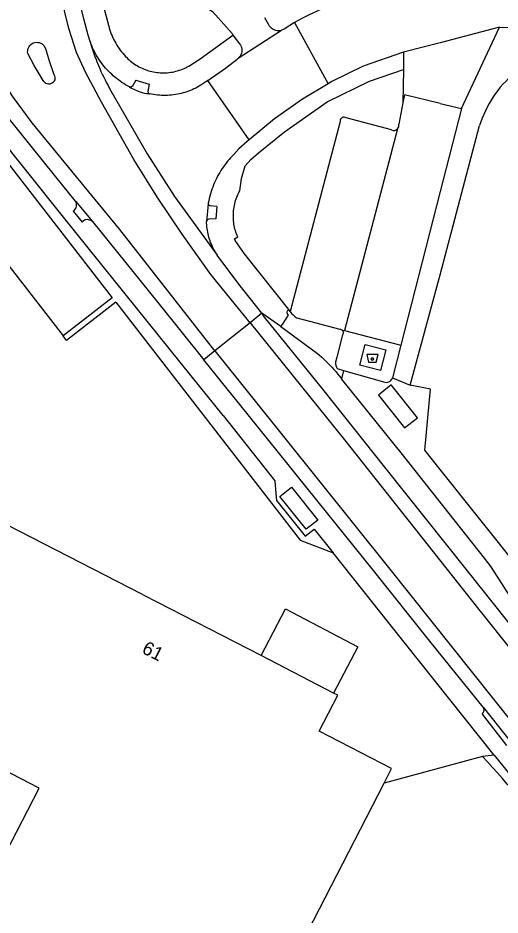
# Model space of a CAD drawing. Extents: x 194485 to 197793, y 468269 to 470822.
# Drawn here: x 194962.7 to 195005.3, y 470132.4 to 470211.6 of the extents above; entities that cross this region are included whole.
import ezdxf

# ---------------------------------------------------------------- set-up
doc = ezdxf.new("R2010")
doc.units = 0
for name, color, linetype in [('BGT grensvlak gebouwinstallatie plus 1', 7, 'Continuous'), ('BGT grensvlak onbegroeid terreindeel', 7, 'Continuous'), ('BGT grensvlak onbegroeid terreindeel LR', 7, 'Continuous'), ('BGT grensvlak pand op maaiveld', 7, 'Continuous'), ('BGT grensvlak wegdeel', 7, 'Continuous'), ('BGT puntobject bak afval apart plaats', 7, 'Continuous'), ('BGT tekst huisnummerreeks', 7, 'Continuous')]:
    doc.layers.add(name, color=color, linetype=linetype)

msp = doc.modelspace()

# ---------------------------------------------------------------- linework, layer by layer
at = {"layer": 'BGT grensvlak gebouwinstallatie plus 1'}
for p, q in [((194984.175, 470155.285), (194986.344, 470159.424)), ((194986.344, 470159.424), (194992.732, 470156.076)), ((194992.732, 470156.076), (194990.587, 470151.983))]:
    msp.add_line(p, q, dxfattribs=at)
for points in [[(194994.538, 470178.29), (194996.858, 470175.385), (194997.985, 470176.286), (194995.666, 470179.191), (194994.538, 470178.29)], [(194985.85, 470169.344), (194986.858, 470170.149), (194989.182, 470167.258), (194988.159, 470166.44), (194985.85, 470169.344)]]:
    msp.add_lwpolyline(points, dxfattribs=at)
at = {"layer": 'BGT grensvlak onbegroeid terreindeel'}
for points in [[(194971.351, 470186.487), (194967.003, 470183.119), (194966.696, 470183.514)], [(194971.351, 470186.487), (194987.623, 470165.482), (194990.541, 470164.356)], [(195004.761, 470146.507), (195003.725, 470146.37), (195003.718, 470146.368)]]:
    msp.add_lwpolyline(points, dxfattribs=at)
msp.add_arc((194976.202, 470119.132), 38.716, 13.77884, 44.70719, dxfattribs=at)
at = {"layer": 'BGT grensvlak onbegroeid terreindeel LR'}
msp.add_line((195003.718, 470146.368), (194995.051, 470144.028), dxfattribs=at)
at = {"layer": 'BGT grensvlak pand op maaiveld'}
msp.add_line((194990.587, 470151.983), (194984.175, 470155.285), dxfattribs=at)
for points in [[(194984.175, 470155.285), (194973.844, 470160.603), (194973.658, 470160.702), (194961.785, 470166.804), (194959.691, 470162.731), (194956.928, 470164.203), (194958.605, 470167.467), (194954.189, 470169.736)], [(194995.051, 470144.028), (194995.708, 470145.307), (194989.3, 470148.605), (194990.947, 470151.798), (194990.587, 470151.983)], [(194944.699, 470140.345), (194959.065, 470132.901), (194964.571, 470143.582), (194950.178, 470151.016), (194944.699, 470140.345)], [(194970.192, 470100.423), (194979.609, 470118.778), (194982.244, 470117.429), (194984.803, 470122.431), (194984.134, 470122.797), (194995.051, 470144.028)]]:
    msp.add_lwpolyline(points, dxfattribs=at)
at = {"layer": 'BGT grensvlak wegdeel'}
for p, q in [((194987.126, 470211.192), (194990.111, 470205.784)), ((194982.161, 470208.034), (194985.981, 470210.514)), ((195005.244, 470210.774), (195000, 470209.408)), ((195001.881, 470203.594), (195005.244, 470210.774)), ((195005.244, 470210.774), (195056.446, 470209.741)), ((195000, 470209.408), (194996.768, 470208.565)), ((194996.768, 470208.565), (194996.745, 470207.046)), ((194993.74, 470206.017), (194996.745, 470207.046)), ((194996.745, 470207.046), (194996.699, 470204.089)), ((194973.112, 470206.102), (194974.3, 470205.73)), ((194983.125, 470200.83), (194979.465, 470206.079)), ((194990.014, 470204.184), (194993.74, 470206.017)), ((194986.237, 470201.529), (194990.014, 470204.184)), ((194996.699, 470204.089), (194996.336, 470202.199)), ((195000, 470204.044), (195001.881, 470203.594)), ((195001.881, 470203.594), (195000, 470196.271)), ((194991.165, 470202.457), (194986.761, 470185.667)), ((194995.707, 470201.717), (194991.695, 470202.757)), ((194983.943, 470199.684), (194986.237, 470201.529)), ((194996.228, 470201.787), (194991.559, 470183.987)), ((194982.785, 470198.545), (194983.286, 470199.084)), ((194983.286, 470199.084), (194983.943, 470199.684)), ((194982.454, 470197.422), (194982.785, 470198.545)), ((194982.293, 470196.324), (194982.454, 470197.422)), ((194982.035, 470195.763), (194982.092, 470195.907)), ((194982.092, 470195.907), (194982.155, 470196.048)), ((194982.155, 470196.048), (194982.222, 470196.187)), ((194982.222, 470196.187), (194982.293, 470196.324)), ((195000, 470196.271), (194996.517, 470182.713)), ((194957.508, 470195.375), (194966.696, 470183.514)), ((194967.781, 470195.428), (194969.297, 470193.605)), ((194979.504, 470195.14), (194979.363, 470193.63)), ((194981.793, 470194.87), (194981.821, 470195.022)), ((194981.821, 470195.022), (194981.853, 470195.173)), ((194981.853, 470195.173), (194981.891, 470195.323)), ((194981.891, 470195.323), (194981.934, 470195.471)), ((194981.934, 470195.471), (194981.982, 470195.618)), ((194981.982, 470195.618), (194982.035, 470195.763)), ((194967.577, 470194.521), (194968.391, 470193.572)), ((194980.266, 470194.93), (194980.19, 470193.859)), ((194981.73, 470194.121), (194981.732, 470194.269)), ((194981.732, 470194.269), (194981.74, 470194.417)), ((194981.74, 470194.417), (194981.752, 470194.564)), ((194981.752, 470194.564), (194981.77, 470194.717)), ((194981.77, 470194.717), (194981.793, 470194.87)), ((194981.731, 470193.974), (194981.73, 470194.121)), ((194981.738, 470193.826), (194981.731, 470193.974)), ((194981.749, 470193.678), (194981.738, 470193.826)), ((194981.765, 470193.532), (194981.749, 470193.678)), ((194981.786, 470193.385), (194981.765, 470193.532)), ((194981.811, 470193.24), (194981.786, 470193.385)), ((194981.841, 470193.095), (194981.811, 470193.24)), ((194981.876, 470192.951), (194981.841, 470193.095)), ((194981.915, 470192.809), (194981.876, 470192.951)), ((194981.959, 470192.667), (194981.915, 470192.809)), ((194982.007, 470192.528), (194981.959, 470192.667)), ((194981.84, 470192.094), (194982.116, 470192.253)), ((194981.899, 470191.955), (194981.84, 470192.094)), ((194982.728, 470190.752), (194981.899, 470191.955)), ((194982.059, 470192.389), (194982.007, 470192.528)), ((194982.116, 470192.253), (194982.059, 470192.389)), ((194986.617, 470185.848), (194982.728, 470190.752)), ((194984.254, 470185.52), (194983.21, 470184.681)), ((194985.936, 470184.339), (194984.254, 470185.52)), ((194986.493, 470185.603), (194986.525, 470185.735)), ((194986.521, 470185.47), (194986.493, 470185.603)), ((194986.525, 470185.735), (194986.617, 470185.848)), ((194986.761, 470185.667), (194986.617, 470185.848)), ((194986.061, 470184.53), (194986.602, 470185.361)), ((194986.602, 470185.361), (194986.521, 470185.47)), ((194983.21, 470184.681), (194980.103, 470182.186)), ((194985.936, 470184.339), (194986.061, 470184.53)), ((194991.294, 470184.055), (194991.559, 470183.987)), ((194991.559, 470183.987), (194996.517, 470182.713)), ((194996.517, 470182.713), (194995.774, 470179.82)), ((194980.103, 470182.186), (194979.129, 470181.403)), ((194990.902, 470180.628), (194991.457, 470180.468)), ((194991.457, 470180.468), (194991.292, 470179.717)), ((194991.457, 470180.468), (194995.104, 470179.419)), ((194995.774, 470179.82), (194997.335, 470179.171)), ((195010.791, 470158.173), (195000, 470171.718)), ((195003.779, 470150.737), (195006.502, 470147.326)), ((195003.699, 470150.132), (195005.859, 470147.365)), ((195004.761, 470146.507), (195007.698, 470142.82))]:
    msp.add_line(p, q, dxfattribs=at)
for points in [[(194980.103, 470182.186), (194971.719, 470192.904), (194967.463, 470198.054), (194963.962, 470202.328), (194962.223, 470204.689), (194960.673, 470207.087), (194959.498, 470209.448), (194958.738, 470211.291), (194958.082, 470213.399), (194957.69, 470215.496), (194957.31, 470218.318), (194957.202, 470221.395), (194957.651, 470224.332), (194958.365, 470227.074), (194959.402, 470229.838), (194960.334, 470232.349), (194964.43, 470242.629), (194967.101, 470249.367), (194974.852, 470268.643)], [(194983.21, 470184.681), (194979.75, 470188.94), (194977.217, 470192.511), (194975.04, 470195.736), (194972.944, 470199.1), (194970.095, 470204.15), (194968.668, 470206.799), (194967.896, 470208.55), (194967.217, 470210.646), (194966.468, 470213.687), (194965.715, 470217.72), (194965.45, 470220.278), (194965.278, 470222.892), (194965.128, 470225.715), (194965.411, 470230.35), (194965.826, 470233.379), (194966.54, 470236.535), (194966.966, 470238.321), (194967.841, 470241.201)], [(194969.745, 470214.63), (194970.372, 470214.671), (194970.532, 470214.657), (194973.192, 470214.524), (194975.982, 470214.15), (194977.779, 470213.574), (194979.905, 470212.147), (194981.631, 470210.207), (194981.681, 470210.081), (194981.691, 470210.068)], [(194969.745, 470214.63), (194970.827, 470210.504), (194970.888, 470210.334), (194970.953, 470210.166), (194971.023, 470209.999), (194971.098, 470209.835), (194971.177, 470209.673), (194971.261, 470209.513), (194971.35, 470209.355), (194971.442, 470209.2), (194971.539, 470209.048), (194971.64, 470208.898), (194971.746, 470208.752), (194971.855, 470208.608), (194971.969, 470208.467), (194972.086, 470208.33), (194972.207, 470208.196), (194972.312, 470208.087), (194972.42, 470207.982), (194972.532, 470207.88), (194972.647, 470207.782), (194972.765, 470207.688), (194972.886, 470207.598), (194973.01, 470207.512), (194973.137, 470207.43), (194973.267, 470207.352), (194973.399, 470207.279), (194973.533, 470207.21), (194973.67, 470207.146), (194973.809, 470207.086), (194973.949, 470207.031), (194974.092, 470206.98), (194974.236, 470206.935), (194974.381, 470206.894), (194974.528, 470206.858), (194974.676, 470206.826), (194974.824, 470206.8), (194974.974, 470206.779), (194975.127, 470206.762), (194975.28, 470206.751), (194975.433, 470206.745), (194975.587, 470206.744), (194975.74, 470206.748), (194975.893, 470206.757), (194976.046, 470206.772), (194976.198, 470206.792), (194976.35, 470206.816), (194976.5, 470206.846), (194976.65, 470206.881), (194976.798, 470206.921), (194976.945, 470206.966), (194977.09, 470207.016), (194977.233, 470207.071), (194977.375, 470207.13), (194977.514, 470207.195), (194977.651, 470207.263), (194977.786, 470207.337), (194978.803, 470207.977), (194981.691, 470210.068)], [(194969.08, 470209.51), (194969.016, 470209.695), (194968.958, 470209.882), (194968.905, 470210.07), (194968.526, 470211.519), (194968.065, 470213.446), (194968.035, 470213.568)], [(194984.471, 470211.62), (194984.845, 470211.003), (194984.907, 470210.9), (194984.98, 470210.806), (194985.065, 470210.722), (194985.159, 470210.648), (194985.261, 470210.586), (194985.371, 470210.538), (194985.485, 470210.503), (194985.609, 470210.482), (194985.734, 470210.476), (194985.859, 470210.487), (194985.981, 470210.514)], [(194987.126, 470211.192), (194986.211, 470210.613), (194986.099, 470210.556), (194985.981, 470210.514)], [(194981.691, 470210.068), (194982.286, 470209.297), (194982.357, 470209.195), (194982.414, 470209.084), (194982.455, 470208.967), (194982.479, 470208.845), (194982.487, 470208.721), (194982.477, 470208.597), (194982.448, 470208.468), (194982.401, 470208.345), (194982.337, 470208.23), (194982.256, 470208.125), (194982.161, 470208.034)], [(194963.584, 470208.442), (194963.567, 470208.569), (194963.57, 470208.697), (194963.593, 470208.823), (194963.635, 470208.944), (194963.695, 470209.057), (194963.772, 470209.159), (194963.863, 470209.249), (194963.968, 470209.323), (194964.082, 470209.38), (194964.207, 470209.42), (194964.338, 470209.439), (194964.469, 470209.437), (194964.599, 470209.415), (194964.723, 470209.372), (194964.839, 470209.311), (194964.944, 470209.231), (194965.035, 470209.136), (194965.16, 470208.805), (194965.453, 470207.9), (194965.893, 470206.6), (194965.948, 470206.493), (194965.978, 470206.376), (194965.982, 470206.255), (194965.96, 470206.137), (194965.912, 470206.026), (194965.842, 470205.928), (194965.751, 470205.848), (194965.646, 470205.789), (194965.529, 470205.754), (194965.407, 470205.747), (194965.286, 470205.766), (194965.173, 470205.811), (194965.072, 470205.88), (194964.989, 470205.97), (194964.928, 470206.076), (194964.152, 470207.396), (194963.584, 470208.442)], [(194972.551, 470205.51), (194972.382, 470205.602), (194972.216, 470205.697), (194972.053, 470205.798), (194971.892, 470205.902), (194971.733, 470206.011), (194971.578, 470206.124), (194971.426, 470206.241), (194971.277, 470206.362), (194971.131, 470206.487), (194970.989, 470206.615), (194970.85, 470206.748), (194970.714, 470206.884), (194970.582, 470207.023), (194970.454, 470207.166), (194970.33, 470207.312), (194970.207, 470207.464), (194970.089, 470207.62), (194969.974, 470207.778), (194969.864, 470207.94), (194969.759, 470208.104), (194969.658, 470208.272), (194969.561, 470208.442), (194969.469, 470208.614), (194969.381, 470208.789), (194969.299, 470208.966), (194969.221, 470209.146), (194969.148, 470209.327), (194969.08, 470209.51)], [(194996.768, 470208.565), (194993.191, 470207.34), (194990.435, 470205.985), (194990.111, 470205.784)], [(194979.465, 470206.079), (194981.027, 470207.168), (194982.054, 470207.957), (194982.161, 470208.034)], [(194973.112, 470206.102), (194972.812, 470205.575), (194972.695, 470205.487), (194972.551, 470205.51)], [(194970.805, 470205.373), (194974.118, 470199.603), (194976.525, 470195.813), (194980.317, 470190.638)], [(194972.551, 470205.51), (194972.676, 470205.434), (194972.803, 470205.362), (194972.932, 470205.295), (194973.064, 470205.233), (194973.198, 470205.175), (194973.334, 470205.122), (194973.472, 470205.074), (194973.611, 470205.03), (194973.752, 470204.992), (194973.894, 470204.958), (194974.037, 470204.93), (194974.181, 470204.906), (194974.326, 470204.888)], [(194974.3, 470205.73), (194974.176, 470205.104), (194974.209, 470204.967), (194974.326, 470204.888)], [(194979.465, 470206.079), (194978.853, 470205.652), (194978.706, 470205.565), (194978.558, 470205.482), (194978.406, 470205.403), (194978.253, 470205.329), (194978.098, 470205.258), (194977.941, 470205.193), (194977.782, 470205.131), (194977.621, 470205.074), (194977.459, 470205.021), (194977.296, 470204.973), (194977.131, 470204.929), (194976.965, 470204.89), (194976.798, 470204.856), (194976.623, 470204.825), (194976.447, 470204.799), (194976.27, 470204.778), (194976.093, 470204.763), (194975.916, 470204.752), (194975.738, 470204.747), (194975.56, 470204.747), (194975.383, 470204.751), (194975.205, 470204.761), (194975.028, 470204.777), (194974.851, 470204.797), (194974.675, 470204.822), (194974.5, 470204.853), (194974.326, 470204.888)], [(194990.111, 470205.784), (194987.841, 470204.405), (194985.373, 470202.67), (194983.125, 470200.83)], [(195000, 470204.044), (194996.836, 470204.8), (194996.699, 470204.089)], [(194967.781, 470195.428), (194966.062, 470197.55), (194961.572, 470203.115)], [(194980.824, 470176.487), (194978.008, 470180.003), (194972.171, 470187.227), (194966.609, 470194.156), (194960.639, 470201.596), (194958.575, 470201.593), (194956.615, 470201.475), (194954.618, 470200.996), (194951.593, 470199.498), (194949.614, 470197.677), (194947.548, 470195.49), (194944.833, 470192.222), (194943.81, 470192.945)], [(194997.335, 470179.171), (195000, 470188.901), (195003.475, 470202.082)], [(194983.125, 470200.83), (194982.939, 470200.678), (194982.209, 470200.048), (194981.762, 470199.53), (194981.622, 470199.387), (194981.486, 470199.24), (194981.354, 470199.09), (194981.225, 470198.937), (194981.1, 470198.78), (194980.979, 470198.621), (194980.862, 470198.459), (194980.749, 470198.294), (194980.64, 470198.126), (194980.535, 470197.955), (194980.434, 470197.782), (194980.338, 470197.607), (194980.246, 470197.429), (194980.154, 470197.24), (194980.067, 470197.049), (194979.985, 470196.855), (194979.908, 470196.659), (194979.836, 470196.462), (194979.77, 470196.263), (194979.708, 470196.062), (194979.652, 470195.859), (194979.6, 470195.655), (194979.555, 470195.45), (194979.514, 470195.244), (194979.504, 470195.14)], [(194961.855, 470198.744), (194971.044, 470186.882), (194966.696, 470183.514)], [(194967.577, 470194.521), (194967.686, 470194.602), (194967.776, 470194.704), (194967.842, 470194.822), (194967.881, 470194.952), (194967.892, 470195.076), (194967.879, 470195.201), (194967.841, 470195.32), (194967.781, 470195.428)], [(194980.266, 470194.93), (194979.652, 470195.005), (194979.557, 470195.049), (194979.504, 470195.14)], [(194969.297, 470193.605), (194969.151, 470193.699), (194969.044, 470193.745), (194968.931, 470193.774), (194968.811, 470193.782), (194968.691, 470193.765), (194968.578, 470193.722), (194968.477, 470193.657), (194968.391, 470193.572)], [(194969.297, 470193.605), (194975.06, 470186.468), (194979.129, 470181.403)], [(194980.19, 470193.859), (194979.559, 470193.814), (194979.428, 470193.757), (194979.363, 470193.63)], [(194980.317, 470190.638), (194980.229, 470190.771), (194980.146, 470190.907), (194980.066, 470191.046), (194979.99, 470191.186), (194979.919, 470191.329), (194979.851, 470191.473), (194979.788, 470191.62), (194979.728, 470191.768), (194979.674, 470191.918), (194979.623, 470192.069), (194979.577, 470192.221), (194979.535, 470192.374), (194979.498, 470192.529), (194979.465, 470192.684), (194979.437, 470192.84), (194979.413, 470192.997), (194979.394, 470193.155), (194979.379, 470193.313), (194979.369, 470193.471), (194979.363, 470193.63)], [(194984.254, 470185.52), (194982.115, 470188.191), (194980.317, 470190.638)], [(195013.657, 470148.669), (195013.632, 470148.701), (195008.272, 470155.415), (195002.417, 470162.774), (194995.107, 470171.924), (194989.638, 470178.812), (194984.496, 470185.183), (194984.254, 470185.52)], [(194991.162, 470184.089), (194987.361, 470185.087), (194987.317, 470185.115)], [(194983.21, 470184.681), (194991.431, 470174.481), (195003.415, 470159.37), (195012.614, 470147.835)], [(194985.936, 470184.339), (194989.152, 470181.972), (194989.345, 470181.806), (194989.535, 470181.637), (194989.722, 470181.465), (194989.905, 470181.289), (194990.086, 470181.109), (194990.263, 470180.927), (194990.434, 470180.744), (194990.603, 470180.558), (194990.767, 470180.369), (194990.929, 470180.177), (194991.087, 470179.982), (194991.241, 470179.784), (194991.292, 470179.717)], [(194991.381, 470183.609), (194990.877, 470181.636), (194990.763, 470181.189)], [(194993.359, 470182.767), (194995.199, 470182.294), (194994.726, 470180.454), (194992.886, 470180.927), (194993.359, 470182.767)], [(194980.103, 470182.186), (194995.417, 470163.066), (195008.412, 470146.777), (195011.013, 470143.378), (195012.291, 470141.604), (195013.489, 470140.049), (195014.802, 470137.871), (195015.953, 470135.015), (195016.771, 470132.688), (195017.416, 470130.499), (195018.186, 470126.596), (195018.393, 470123.463), (195018.347, 470121.309), (195018.055, 470116.849), (195017.272, 470111.447), (195016.742, 470107.507), (195015.177, 470097.695), (195012.49, 470079.726), (195009.724, 470061.761), (195006.68, 470042.048), (195005.475, 470034.063)], [(195003.779, 470150.737), (194999.078, 470156.565), (194994.1, 470162.798), (194987.389, 470171.124), (194986.557, 470172.156), (194982.172, 470177.615), (194980.679, 470179.474), (194979.129, 470181.403)], [(195012.995, 470149.826), (195011.227, 470152.608), (195011.002, 470152.961), (195004.509, 470163.114), (195003.915, 470163.901), (194996.656, 470173.036), (194991.392, 470179.584), (194991.292, 470179.717)], [(195000, 470171.718), (194998.65, 470173.413), (194999.125, 470178.822), (194997.335, 470179.171)], [(194980.824, 470176.487), (194985.401, 470170.715), (194985.487, 470169.604), (194985.535, 470168.985), (194988.062, 470165.824), (194988.862, 470166.464), (194990.541, 470164.356)], [(195004.761, 470146.507), (194995.548, 470158.072), (194990.541, 470164.356)], [(195003.699, 470150.132), (195003.791, 470150.232), (195003.848, 470150.356), (195003.865, 470150.488), (195003.841, 470150.619), (195003.779, 470150.737)]]:
    msp.add_lwpolyline(points, dxfattribs=at)
for centre, radius, start, end in [((195009.768, 470168.653), 48.19, 90.43857, 118.02459), ((194987.253, 470214.66), 18.889, 195.82055, 209.44868), ((195012.679, 470199.294), 9.617, 129.53792, 163.15052), ((194991.496, 470202.491), 0.333, 53.22626, 185.79674), ((194995.923, 470202.087), 0.428, 315.46684, 15.15559), ((194995.923, 470202.086), 0.427, 239.66476, 315.63976), ((194988.441, 470186.803), 2.028, 214.07099, 236.3427), ((194991.157, 470183.795), 0.294, 62.1691, 88.94282), ((194991.157, 470183.797), 0.292, 320.04217, 62.03367), ((194991.602, 470181.099), 0.843, 173.87829, 213.95376), ((194995.217, 470179.985), 0.578, 258.68746, 307.64276), ((194995.205, 470180), 0.597, 307.69529, 342.42609)]:
    msp.add_arc(centre, radius, start, end, dxfattribs=at)
at = {"layer": 'BGT puntobject bak afval apart plaats'}
msp.add_lwpolyline([(194994.329, 470181.206), (194994.504, 470181.881), (194993.504, 470181.881), (194993.679, 470181.206)], close=True, dxfattribs=at)
msp.add_circle((194994.004, 470181.481), 0.1, dxfattribs=at)
for start, end in [(0, 180), (180, 0)]:
    msp.add_arc((194994.004, 470181.481), 0.1, start, end, dxfattribs=at)

# ---------------------------------------------------------------- texts
at = {"layer": 'BGT tekst huisnummerreeks'}
msp.add_text('61', height=1.2, rotation=332.8, dxfattribs=at).set_placement((194973.57, 470155.566))

doc.saveas('drawing.dxf')
